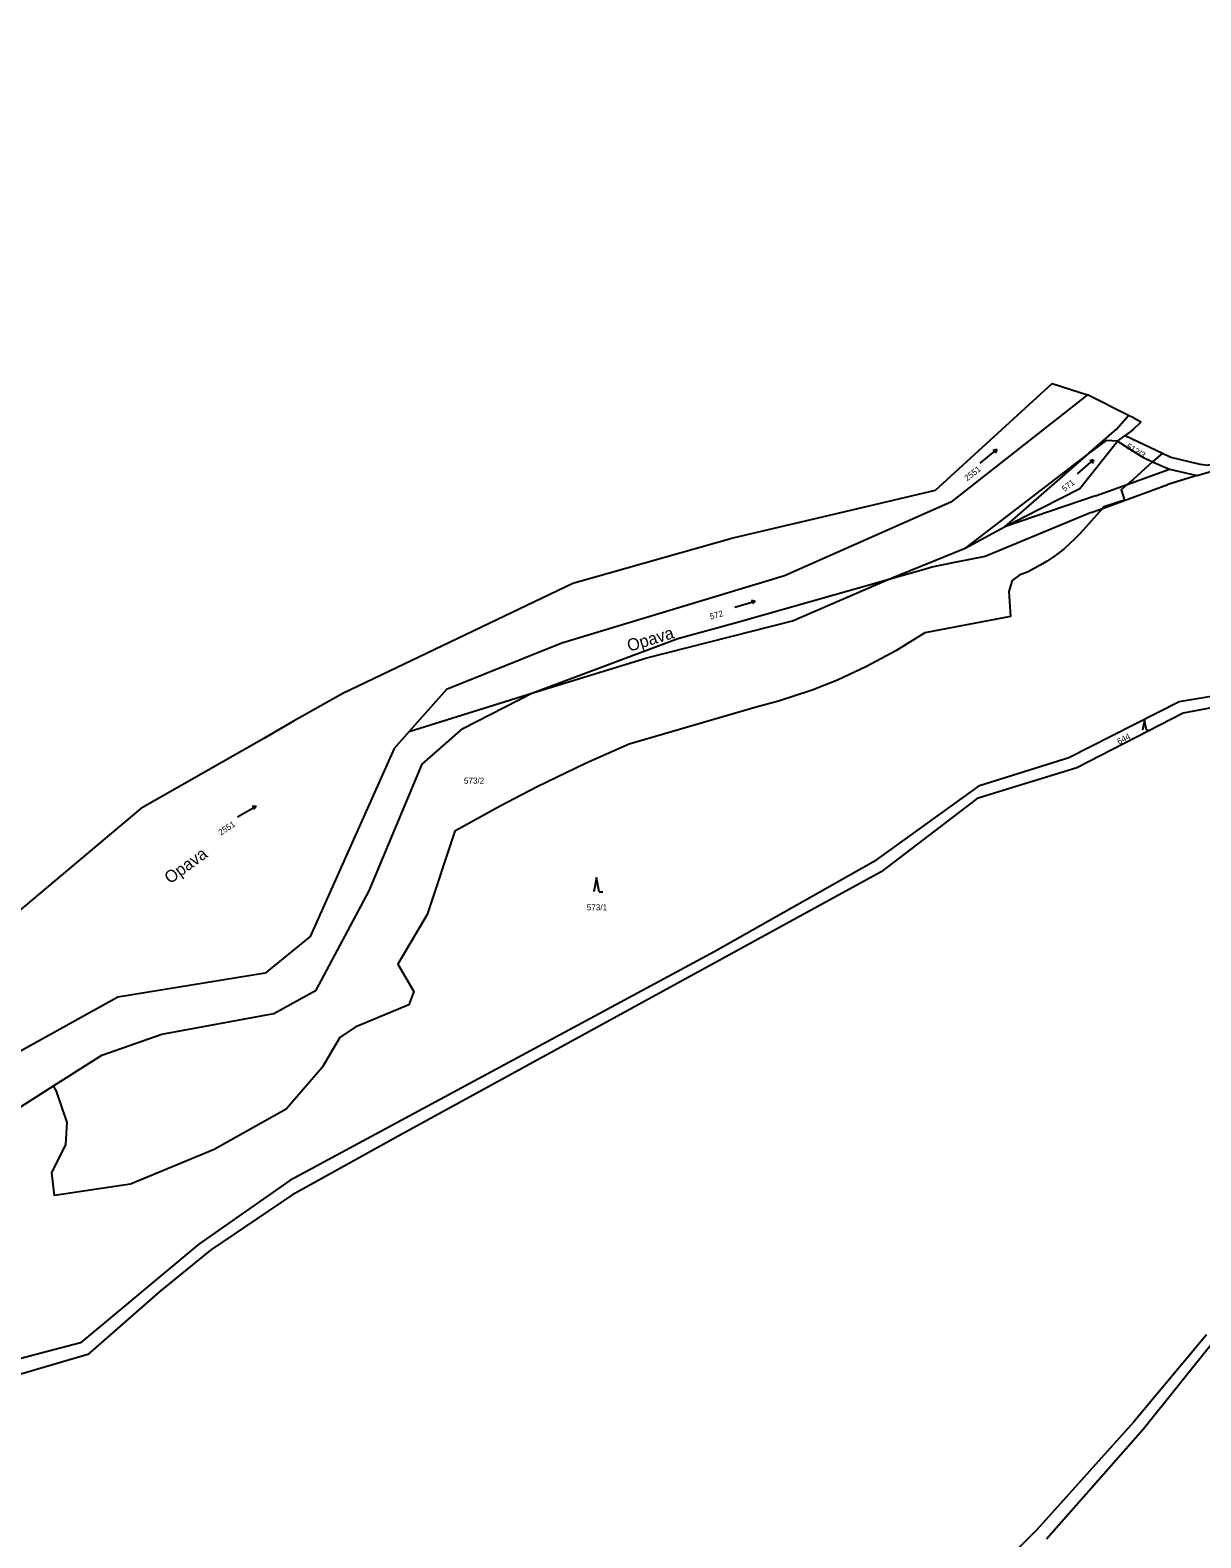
# Model space of a CAD drawing. Extents: x -520431 to -517205, y -1075927 to -1074013.
# Drawn here: x -519363.6 to -519035.6, y -1074823.4 to -1074401.2 of the extents above; entities that cross this region are included whole.
import ezdxf

# ---------------------------------------------------------------- set-up
doc = ezdxf.new("R2010")
doc.units = 0
for name, color, linetype in [('Hranice parcel', 7, 'Continuous'), ('Parcelní čísla', 7, 'Continuous'), ('Pop  PČ popisy', 7, 'Continuous'), ('Vnitřní kresba', 7, 'Continuous'), ('Značky kultur', 7, 'Continuous')]:
    doc.layers.add(name, color=color, linetype=linetype)

msp = doc.modelspace()

# ---------------------------------------------------------------- linework, layer by layer
at = {"layer": 'Hranice parcel'}
for p, q in [((-519077.28, -1074500.16), (-519110.07, -1074530.16)), ((-519077.28, -1074500.16), (-519067.41, -1074503.37)), ((-519055.87, -1074509.14), (-519067.41, -1074503.37)), ((-519054.33, -1074509.91), (-519055.87, -1074509.14)), ((-519054.71, -1074513.16), (-519052.35, -1074510.89)), ((-519054.33, -1074509.91), (-519052.35, -1074510.89)), ((-519059, -1074516.32), (-519056.85, -1074514.74)), ((-519054.71, -1074513.16), (-519056.85, -1074514.74)), ((-519056.85, -1074514.74), (-519046.37, -1074519.68)), ((-519059, -1074516.32), (-519052.1, -1074520.76)), ((-519046.37, -1074519.68), (-519049.16, -1074522.08)), ((-519046.37, -1074519.68), (-519044, -1074520.8)), ((-519049.16, -1074522.08), (-519054.62, -1074527.04)), ((-519052.1, -1074520.76), (-519049.16, -1074522.08)), ((-519049.16, -1074522.08), (-519044.43, -1074524.2)), ((-519044.43, -1074524.2), (-519036.6, -1074525.93)), ((-519036.6, -1074525.93), (-519024.03, -1074522.12)), ((-519110.07, -1074530.16), (-519133.75, -1074535.73)), ((-519133.75, -1074535.73), (-519166.36, -1074543.4)), ((-519166.36, -1074543.4), (-519211.57, -1074556.18)), ((-519211.57, -1074556.18), (-519276.01, -1074587)), ((-519332.62, -1074619.2), (-519399.98, -1074675.85)), ((-519357.01, -1074696.85), (-519343.53, -1074688.29)), ((-519374.84, -1074708.18), (-519357.01, -1074696.85)), ((-519356.23, -1074698.34), (-519357.01, -1074696.85))]:
    msp.add_line(p, q, dxfattribs=at)
for points in [[(-518886.51, -1074401.23), (-518900.35, -1074419.35), (-518936.48, -1074494.71), (-518944.81, -1074522.23), (-518964.42, -1074545.59), (-518994.02, -1074577.6), (-519014.03, -1074582.35), (-519015.8, -1074585), (-519041.66, -1074589.31), (-519072.61, -1074604.97), (-519097.89, -1074612.94), (-519127.28, -1074634.12), (-519171.73, -1074659.2), (-519290.83, -1074723.35), (-519316.3, -1074741.22), (-519349.48, -1074768.81), (-519373.36, -1074775.06), (-519417.58, -1074772.1), (-519455.35, -1074775.46)], [(-519067.41, -1074503.37), (-519105.65, -1074533.39), (-519152.21, -1074554), (-519214.64, -1074572.91), (-519246.93, -1074585.91), (-519257.36, -1074597.62), (-519261.65, -1074602.43), (-519285.18, -1074655.06), (-519297.71, -1074665.27), (-519339.06, -1074672.04), (-519380.82, -1074695.22), (-519424.21, -1074713.57), (-519476.17, -1074731.36), (-519496.72, -1074735.88), (-519546.73, -1074745.25)], [(-519059, -1074516.32), (-519062.17, -1074516.12), (-519067.05, -1074519.75), (-519101.63, -1074546.3)], [(-519101.63, -1074546.3), (-519090.66, -1074540.34), (-519069.52, -1074529.58), (-519059, -1074516.32)], [(-519044, -1074520.8), (-519036.29, -1074522.63), (-519035.72, -1074522.77), (-519033.79, -1074523.03), (-519024.56, -1074520.67)], [(-519054.62, -1074527.04), (-519056.24, -1074528.45), (-519057.98, -1074529.97), (-519057.03, -1074532.81), (-519062.81, -1074534.75), (-519063.19, -1074535.17), (-519069.49, -1074542.24), (-519070.9, -1074543.72), (-519072.37, -1074545.12), (-519073.91, -1074546.46), (-519075.5, -1074547.73), (-519077.15, -1074548.92), (-519078.85, -1074550.04), (-519080.6, -1074551.07), (-519084.2, -1074552.99), (-519086.36, -1074553.8), (-519088.43, -1074555.34), (-519089.43, -1074558.4), (-519088.9, -1074565.42), (-519112.9, -1074569.96), (-519121.11, -1074575), (-519129.24, -1074579.43), (-519137.36, -1074583.22), (-519144.49, -1074586.05), (-519153.97, -1074589.16), (-519160.16, -1074590.8), (-519195.77, -1074601.15), (-519208.02, -1074606.63), (-519221.52, -1074613.13), (-519231.89, -1074618.51), (-519244.61, -1074625.55), (-519252.4, -1074648.91), (-519260.57, -1074662.83), (-519256.14, -1074670.44), (-519257.52, -1074674.2), (-519272.57, -1074680.39), (-519276.84, -1074683.33), (-519281.81, -1074691.7), (-519291.86, -1074703.4), (-519312, -1074714.67), (-519335.48, -1074724.42), (-519356.73, -1074727.6), (-519357.51, -1074721.23), (-519353.61, -1074713.32), (-519353.21, -1074707.17), (-519356.23, -1074698.34)], [(-519343.53, -1074688.29), (-519326.71, -1074682.35), (-519295.36, -1074676.63), (-519283.45, -1074670.04), (-519268.6, -1074642.28), (-519253.78, -1074606.75), (-519242.4, -1074596.79), (-519223.06, -1074586.87), (-519190.85, -1074576.98), (-519150.05, -1074566.62), (-519123.04, -1074554.95), (-519101.63, -1074546.3)], [(-519012.26, -1074587.2), (-519040.61, -1074592.47), (-519070.39, -1074607.78), (-519098.29, -1074616.37), (-519125.16, -1074636.94), (-519261.18, -1074711.28), (-519290.23, -1074727.46), (-519313.08, -1074742.88), (-519327.19, -1074754.33), (-519347.38, -1074772.11), (-519371.59, -1074779.17), (-519415.72, -1074775.45), (-519453.65, -1074778.32), (-519473.05, -1074780.6), (-519522.57, -1074799.3), (-519557.67, -1074807.11), (-519597.1, -1074804.82), (-519636.88, -1074805.37)], [(-519276.01, -1074587), (-519289.82, -1074594.7), (-519298.1, -1074599.61), (-519332.62, -1074619.2)]]:
    msp.add_lwpolyline(points, dxfattribs=at)
at = {"layer": 'Vnitřní kresba'}
for p, q in [((-519059.28, -1074512.98), (-519055.87, -1074509.14)), ((-519067.05, -1074519.75), (-519059.28, -1074512.98)), ((-519067.05, -1074519.75), (-519090.66, -1074540.34)), ((-519056.24, -1074528.45), (-519044.43, -1074524.2)), ((-519065.17, -1074531.66), (-519056.24, -1074528.45)), ((-519063.19, -1074535.17), (-519044.86, -1074528.43)), ((-519036.6, -1074525.93), (-519044.86, -1074528.43)), ((-519065.17, -1074531.66), (-519090.66, -1074540.34)), ((-519066.32, -1074536.32), (-519096.07, -1074548.6)), ((-519066.32, -1074536.32), (-519063.19, -1074535.17)), ((-519096.07, -1074548.6), (-519104.59, -1074550.26)), ((-519123.04, -1074554.95), (-519111.41, -1074551.72)), ((-519104.59, -1074550.26), (-519111.41, -1074551.72)), ((-519165.46, -1074566.98), (-519125.3, -1074555.58)), ((-519125.3, -1074555.58), (-519123.04, -1074554.95)), ((-519182.16, -1074571.58), (-519165.46, -1074566.98)), ((-519223.06, -1074586.87), (-519182.16, -1074571.58)), ((-519257.36, -1074597.62), (-519223.06, -1074586.87)), ((-519034.06, -1074766.63), (-519054.4, -1074790.98)), ((-519031.78, -1074768.18), (-519051.77, -1074793.09)), ((-519054.4, -1074790.98), (-519081.6, -1074821.23)), ((-519051.77, -1074793.09), (-519078.85, -1074823.82)), ((-519081.6, -1074821.23), (-519118.29, -1074857.97))]:
    msp.add_line(p, q, dxfattribs=at)
at = {"layer": 'Značky kultur'}
for p, q in [((-519097.46, -1074522.45), (-519092.8, -1074518.68)), ((-519092.8, -1074518.68), (-519093.88, -1074518.9)), ((-519092.8, -1074518.68), (-519093.24, -1074519.68)), ((-519070.19, -1074525.47), (-519065.66, -1074521.54)), ((-519065.66, -1074521.54), (-519066.72, -1074521.8)), ((-519065.66, -1074521.54), (-519066.07, -1074522.56)), ((-519166.21, -1074562.77), (-519160.44, -1074561.12)), ((-519160.44, -1074561.12), (-519161.52, -1074560.9)), ((-519160.44, -1074561.12), (-519161.24, -1074561.87)), ((-519051.4, -1074594.48), (-519051.92, -1074597.28)), ((-519050.88, -1074597.28), (-519051.4, -1074594.48)), ((-519050.88, -1074597.28), (-519050.18, -1074597.28)), ((-519305.51, -1074621.54), (-519300.31, -1074618.54)), ((-519300.31, -1074618.54), (-519301.41, -1074618.59)), ((-519300.31, -1074618.54), (-519300.91, -1074619.46)), ((-519204.92, -1074638.49), (-519205.67, -1074642.49)), ((-519204.17, -1074642.49), (-519204.92, -1074638.49)), ((-519204.17, -1074642.49), (-519203.17, -1074642.49))]:
    msp.add_line(p, q, dxfattribs=at)

# ---------------------------------------------------------------- texts
at = {"layer": 'Parcelní čísla'}
for s, rotation, p in [('512/3', 329, (-519056.68, -1074518.25)), ('2551', 38, (-519101.05, -1074527.58)), ('571', 39, (-519073.73, -1074530.59)), ('572', 16, (-519172.92, -1074566.32)), ('644', 28, (-519058.51, -1074601.32)), ('2551', 34, (-519310.14, -1074626.82))]:
    msp.add_text(s, height=1.7, rotation=rotation, dxfattribs=at).set_placement(p)
for s, p in [('573/2', (-519242.07, -1074612.24)), ('573/1', (-519207.64, -1074647.72))]:
    msp.add_text(s, height=1.7, dxfattribs=at).set_placement(p)
at = {"layer": 'Pop  PČ popisy'}
for rotation, p in [(17, (-519195.75, -1074575.33)), (36, (-519324.42, -1074640.45))]:
    msp.add_text('Opava', height=3.4, rotation=rotation, dxfattribs=at).set_placement(p)

doc.saveas('drawing.dxf')
